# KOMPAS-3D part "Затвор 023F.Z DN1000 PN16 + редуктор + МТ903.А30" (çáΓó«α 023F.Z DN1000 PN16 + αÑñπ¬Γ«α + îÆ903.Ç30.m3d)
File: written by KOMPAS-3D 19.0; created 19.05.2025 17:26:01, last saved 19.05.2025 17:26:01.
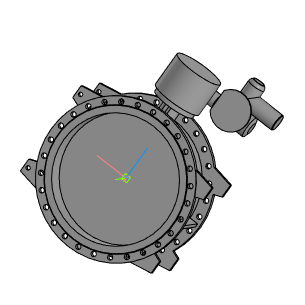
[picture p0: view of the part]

Document properties: Полное имя файла: Затвор 023F.Z DN1000 PN16 + редуктор + МТ903.А30.a3d

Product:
- Part/product: Затвор 023F.Z DN1000 PN16 + редуктор + МТ903.А30
    Масса: 1761.21

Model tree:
1. Операция без истории:1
